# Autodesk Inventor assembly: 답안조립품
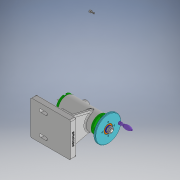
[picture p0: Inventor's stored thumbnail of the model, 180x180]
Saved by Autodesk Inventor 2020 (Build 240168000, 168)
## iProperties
Created: 2021-11
Part Number: 답안조립품
Document SubType Name: Assembly
Designer: user
Author: user
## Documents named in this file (18)
- C:\Users\user\Desktop\711112V1001\답안조립품.iam
- C:\Users\user\Desktop\711112V1001\나사.ipt
- C:\Users\user\Desktop\711112V1001\나사축.ipt
- C:\Users\user\Desktop\711112V1001\너트 M8.ipt
- C:\Users\user\Desktop\711112V1001\돌림판.ipt
- C:\Users\user\Desktop\711112V1001\멈춤나사 M3.ipt
- C:\Users\user\Desktop\711112V1001\본체.ipt
- C:\Users\user\Desktop\711112V1001\볼트 M3.ipt
- C:\Users\user\Desktop\711112V1001\부시.ipt
- C:\Users\user\Desktop\711112V1001\센터.ipt
- C:\Users\user\Desktop\711112V1001\센터홀더.ipt
- C:\Users\user\Desktop\711112V1001\슬리브.ipt
- C:\Users\user\Desktop\711112V1001\와셔.ipt
- C:\Users\user\Desktop\711112V1001\중공축.ipt
- C:\Users\user\Desktop\711112V1001\커버.ipt
- C:\Users\user\Desktop\711112V1001\키 4 x 4 x 10.ipt
- C:\Users\user\Desktop\711112V1001\플랜지.ipt
- C:\Users\user\Desktop\711112V1001\핸들.ipt
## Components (2 placed, 2 different names)
1. 플랜지:1
2. 핸들:1 — 플러쉬:1
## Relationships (1: Flush 1)
- 플러쉬:1 [Flush]: 핸들:1
